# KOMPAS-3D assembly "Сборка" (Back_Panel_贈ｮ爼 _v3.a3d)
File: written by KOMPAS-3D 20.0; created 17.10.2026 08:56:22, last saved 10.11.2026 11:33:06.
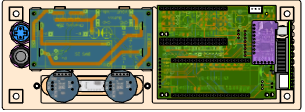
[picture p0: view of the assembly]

Document properties: Полное имя файла: D:\RicWork\Project-EPS32\box_compas\сборки компонентов\Back_Panel_Сборка_v3.a3d

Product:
- Part/product: Сборка
    Масса: 1.86269
  - Component [assembly]: Сборка  | Масса: 0.264091; source file: ILI9341_81_50_DevBoard dual cpu.a3d
  - Component [assembly]: Сборка  | Масса: 0.245268; source file: ILI9341_86_50_DevBoard.a3d
  - Component [assembly]: Сборка  | Масса: 0.0237077; source file: ..\переключатели и кнопки\button_momentary self-reset 12 asm.a3d
  - Component [assembly]: Сборка  | Масса: 0.0750813; source file: ..\корпус\крышка на батарейный отсек v3 asm.a3d
  - Component [detail]: Деталь  | Масса: 0.0229921; source file: ..\корпус\крышка на монитор.m3d
  - Component [detail]: Деталь  | Масса: 0.0739347; source file: ..\корпус\крышка на батарейный отсек v2.m3d
  - Component [detail]: Деталь  | qty 4  | Масса: 0.000148431; source file: ..\прочее\Латунные рифленые гайки HUI JI.m3d
  - Component [assembly]: Сборка  | Масса: 0.108754; source file: панель кнопок asm.a3d
  - Component [assembly]: Сборка  | Масса: 0.0501556; source file: panel_ir_sd_jack_asm.a3d
  - Component [assembly]: Сборка  | Масса: 0.425781; source file: ..\ups 18650\my_ups_asm.a3d
  - Component [detail]: Деталь  | Масса: 0.0197779; source file: ..\разъемы\USB-C_Type-C.m3d
  - Component [detail]: Деталь  | Масса: 0.0223332; source file: ..\корпус\п-стойка_2_r.m3d
  - Component [detail]: Деталь  | Масса: 0.0248378; source file: ..\корпус\п-стойка_2_l.m3d
  - Component [assembly]: Сборка  | Масса: 0.120303; source file: ..\wifi\antenna wifi_asm.a3d
  - Component [detail]: Деталь  | Материал: Фанера, береза,ФСФ ВВ/С ГОСТ 3916.1-2018 (density 760 kg/m3); Масса: 0.0216848; source file: ..\корпус\back_panel_v3.m3d
  - Component [assembly]: Сборка  | Масса: 0.290133; source file: ILI9341_81_50_DevBoard.a3d
  - Component [assembly]: Сборка  | Масса: 0.0732619; source file: панель кнопок v2 asm.a3d

Referenced files in D:\RicWork\Project-EPS32\box_compas\корпус\: back_panel_v3.m3d, п-стойка_2_l.m3d, п-стойка_2_r.m3d, крышка на батарейный отсек v2.m3d, крышка на монитор.m3d, крышка на батарейный отсек v3 asm.a3d
Referenced files in D:\RicWork\Project-EPS32\box_compas\wifi\: antenna wifi_asm.a3d
Referenced files in D:\RicWork\Project-EPS32\box_compas\переключатели и кнопки\: button_momentary self-reset 12 asm.a3d
Referenced files in D:\RicWork\Project-EPS32\box_compas\сборки компонентов\: panel_ir_sd_jack_asm.a3d, панель кнопок asm.a3d, ILI9341_81_50_DevBoard.a3d, ILI9341_86_50_DevBoard.a3d, панель кнопок v2 asm.a3d, ILI9341_81_50_DevBoard dual cpu.a3d
Referenced files in D:\RicWork\Project-EPS32\box_compas\прочее\: Латунные рифленые гайки HUI JI.m3d
Referenced files in D:\RicWork\Project-EPS32\box_compas\разъемы\: USB-C_Type-C.m3d
Referenced files in D:\RicWork\Project-EPS32\box_compas\ups 18650\: my_ups_asm.a3d
Referenced files in D:\myProjects\Progect_esp32\box_compas\прочее\: Латунные рифленые гайки HUI JI.m3d
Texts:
  Деталь (1)
  Деталь (2)
  Деталь (3)
  Деталь (4)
